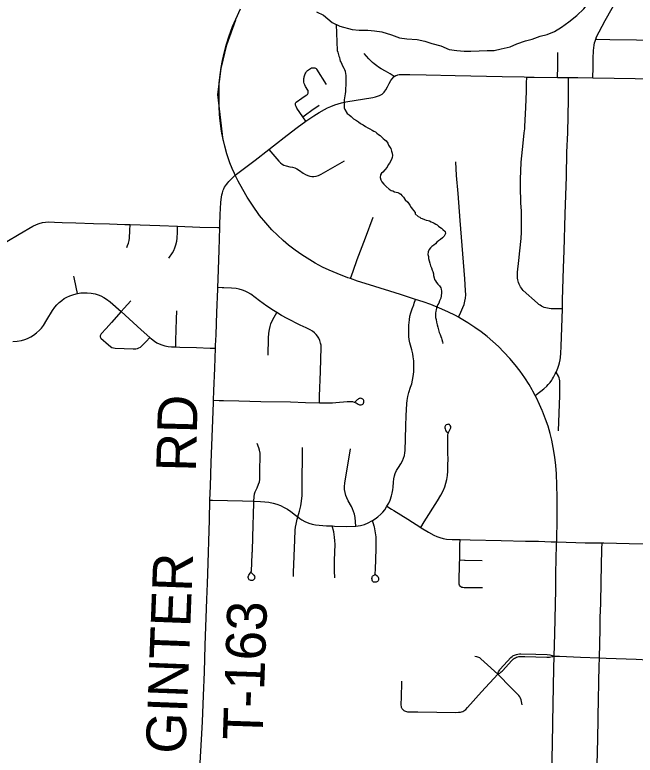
# Model space of a CAD drawing. Extents: x -483 to 680, y 0 to 440.
# Drawn here: x 289.1 to 333.5, y 277.4 to 330.4 of the extents above; entities that cross this region are included whole.
import ezdxf

# ---------------------------------------------------------------- set-up
doc = ezdxf.new("R2010")
doc.units = 0
for name, color, linetype in [('Default', 7, 'Continuous'), ('GM_X_City_Street', 7, 'Continuous'), ('GM_X_County_Road', 7, 'Continuous'), ('GM_X_Major_River', 7, 'Continuous'), ('GM_X_Minor_River', 7, 'Continuous'), ('GM_X_State_Route', 7, 'Continuous'), ('GM_X_Township_Road', 7, 'Continuous'), ('GM_X_Township_Road_Text', 7, 'Continuous')]:
    doc.layers.add(name, color=color, linetype=linetype)

msp = doc.modelspace()

# ---------------------------------------------------------------- linework, layer by layer
at = {"layer": 'Default'}
msp.add_lwpolyline([(304.059, 321.427), (303.678, 324.697), (303.918, 326.545), (304.31, 328.234), (304.975, 330.024)], dxfattribs=at)
at = {"layer": 'GM_X_City_Street'}
for points in [[(330.516, 325.883), (330.519, 326.002), (330.532, 326.498), (330.53, 327.273), (330.558, 327.829), (330.577, 328.017), (330.605, 328.226), (330.636, 328.385), (330.666, 328.504), (330.716, 328.659), (330.778, 328.811), (330.952, 329.171), (331.402, 329.986), (331.883, 330.857), (332.099, 331.245), (332.546, 332.052), (334.247, 335.125), (334.953, 336.404), (335.502, 337.375), (335.718, 337.757), (336.69, 339.528), (337.124, 340.318), (337.77, 341.496), (338.23, 342.335)], [(330.716, 328.659), (330.788, 328.656), (331.719, 328.623), (333.644, 328.598), (335.071, 328.571), (337.473, 328.53), (337.597, 328.527)], [(316.297, 325.978), (316.007, 326.164), (315.668, 326.351), (315.353, 326.526), (315.18, 326.642), (315.049, 326.734), (314.871, 326.876), (314.74, 326.989), (314.577, 327.147), (314.477, 327.249), (314.305, 327.437), (314.149, 327.622)], [(327.982, 325.907), (327.983, 325.985), (327.995, 326.611), (328.007, 327.211), (327.999, 327.702)], [(309.759, 323.098), (309.341, 323.706), (309.271, 323.832), (309.247, 323.881), (309.233, 323.929), (309.227, 323.991), (309.231, 324.031), (309.239, 324.071), (309.255, 324.109), (309.287, 324.149), (309.684, 324.423), (309.995, 324.632), (310.087, 324.701), (310.117, 324.738), (310.136, 324.778), (310.149, 324.827), (310.152, 324.878), (310.146, 324.923), (310.138, 324.969), (310.125, 325.01), (309.957, 325.256), (309.891, 325.377), (309.871, 325.431), (309.855, 325.485), (309.841, 325.562), (309.834, 325.638), (309.831, 325.716), (309.836, 325.793), (309.839, 325.842), (309.847, 325.898), (309.859, 325.957), (309.877, 326.023), (309.903, 326.106), (309.931, 326.175), (309.963, 326.239), (309.993, 326.29), (310.022, 326.328), (310.06, 326.374), (310.1, 326.411), (310.162, 326.459), (310.388, 326.588), (310.443, 326.604), (310.493, 326.61), (310.533, 326.61), (310.583, 326.604), (310.626, 326.592), (310.672, 326.574), (310.702, 326.55), (310.745, 326.504), (311.431, 325.403)], [(328.33, 309.367), (327.997, 309.37), (327.533, 309.374), (327.395, 309.387), (327.27, 309.405), (327.15, 309.433), (327.033, 309.472), (326.926, 309.517), (326.835, 309.567), (326.739, 309.626), (326.643, 309.685), (326.544, 309.763), (325.531, 310.681), (325.456, 310.772), (325.398, 310.853), (325.343, 310.936), (325.278, 311.04), (325.239, 311.128), (325.195, 311.238), (325.158, 311.339), (325.135, 311.448), (325.121, 311.553), (325.111, 311.657), (325.11, 311.734), (325.123, 311.978), (325.217, 312.81), (325.289, 313.523), (325.37, 314.391), (325.399, 314.858), (325.409, 315.42), (325.398, 316.354), (325.368, 316.945), (325.328, 318.124), (325.332, 318.651), (325.347, 319.209), (325.391, 319.859), (325.533, 321.219), (325.606, 321.962), (325.639, 322.239), (325.653, 322.393), (325.723, 323.759), (325.756, 324.94), (325.771, 325.499), (325.79, 325.942)], [(326.389, 303.168), (326.792, 303.48), (327.011, 303.65), (327.213, 303.837), (327.324, 303.951), (327.446, 304.089), (327.569, 304.253), (327.632, 304.353), (327.696, 304.468), (327.826, 304.712), (327.878, 304.83), (327.95, 304.993), (328.005, 305.129), (328.077, 305.327), (328.127, 305.512), (328.174, 305.713), (328.202, 305.889), (328.226, 306.186), (328.255, 306.681), (328.33, 309.367), (328.348, 309.976), (328.417, 312.308), (328.454, 313.52), (328.539, 316.131), (328.617, 318.836), (328.661, 320.577), (328.71, 321.945), (328.772, 324.369), (328.775, 325.396), (328.777, 325.904)], [(309.759, 323.098), (309.947, 323.236), (310.402, 323.573), (310.924, 323.936)], [(309.976, 322.783), (309.818, 323.012), (309.759, 323.098)], [(307.327, 320.762), (307.624, 320.413), (308.048, 319.915), (308.156, 319.809), (308.273, 319.718), (308.401, 319.644), (308.57, 319.579), (308.838, 319.522), (309.023, 319.485), (309.178, 319.442), (309.327, 319.381), (309.517, 319.263), (309.793, 319.061), (309.95, 318.969), (310.115, 318.898), (310.259, 318.858), (310.407, 318.836), (310.556, 318.834), (310.703, 318.853), (310.875, 318.904), (311.067, 318.992), (312.067, 319.561), (312.738, 319.955)], [(320.889, 308.769), (321.053, 309.119), (321.212, 309.455), (321.297, 309.684), (321.361, 309.919), (321.396, 310.129), (321.412, 310.372), (321.402, 310.679), (321.345, 311.516), (321.022, 315.671), (320.866, 317.624), (320.762, 318.895), (320.697, 319.888)], [(288.574, 314.18), (289.452, 314.711), (290.449, 315.278), (290.696, 315.399), (290.896, 315.473), (291.132, 315.534), (291.342, 315.564), (291.586, 315.575), (291.987, 315.563), (292.546, 315.544), (293.509, 315.505), (294.782, 315.469), (295.931, 315.433), (297.017, 315.398), (297.393, 315.386), (299.534, 315.315), (300.801, 315.271), (302.391, 315.215), (303.669, 315.179), (303.818, 315.175)], [(313.164, 311.525), (313.361, 312.066), (313.658, 312.882), (314.242, 314.451), (314.803, 315.929)], [(297.16, 313.749), (297.222, 313.89), (297.289, 314.062), (297.335, 314.241), (297.358, 314.424), (297.378, 314.977), (297.393, 315.386)], [(300.181, 312.979), (300.436, 313.368), (300.526, 313.53), (300.611, 313.729), (300.678, 313.935), (300.741, 314.207), (300.769, 314.422), (300.786, 314.855), (300.801, 315.271)], [(293.642, 310.457), (293.549, 310.903), (293.405, 311.603), (293.384, 311.694)], [(310.945, 302.654), (310.96, 303.117), (311.015, 304.888), (311.047, 305.756), (311.073, 306.593), (311.061, 306.773), (311.033, 306.92), (310.977, 307.092), (310.903, 307.257), (310.81, 307.412), (310.718, 307.529), (310.59, 307.657), (310.448, 307.768), (310.294, 307.862), (309.987, 308.005), (309.561, 308.196), (308.646, 308.664), (308.237, 308.89), (307.89, 309.104), (307.653, 309.249), (307.185, 309.559), (306.651, 309.938), (306.034, 310.405), (305.829, 310.538), (305.639, 310.634), (305.441, 310.71), (305.206, 310.775), (304.996, 310.814), (304.66, 310.842), (304.103, 310.868), (303.979, 310.871), (303.683, 310.879)], [(289.019, 307.027), (289.325, 307.053), (289.628, 307.103), (289.863, 307.167), (290.062, 307.244), (290.308, 307.368), (290.49, 307.478), (290.709, 307.646), (290.914, 307.83), (291.058, 307.987), (291.203, 308.183), (291.452, 308.574), (291.853, 309.243), (292.013, 309.476), (292.154, 309.647), (292.333, 309.827), (292.504, 309.969), (292.689, 310.096), (292.884, 310.207), (293.088, 310.3), (293.299, 310.373), (293.545, 310.439), (293.642, 310.457), (293.886, 310.5), (294.107, 310.518), (294.33, 310.514), (294.612, 310.482), (294.89, 310.428), (295.104, 310.369), (295.312, 310.289), (295.509, 310.186), (295.721, 310.049), (295.971, 309.857), (296.754, 309.166), (298.196, 307.864), (298.822, 307.316), (298.92, 307.23), (299.138, 307.06), (299.317, 306.944), (299.478, 306.861), (299.676, 306.784), (299.883, 306.727), (300.125, 306.683), (300.37, 306.657), (300.665, 306.647), (300.958, 306.636), (302.14, 306.599), (303.134, 306.561), (303.508, 306.546)], [(296.754, 309.166), (296.983, 309.42), (297.208, 309.67), (297.449, 309.948)], [(313.541, 293.821), (313.886, 293.879), (314.18, 293.954), (314.433, 294.063), (314.704, 294.207), (314.754, 294.237), (314.939, 294.352), (315.133, 294.498), (315.339, 294.682), (315.486, 294.836), (315.618, 295.003), (315.78, 295.247), (315.905, 295.471), (316.004, 295.694), (316.107, 295.983), (316.16, 296.189), (316.201, 296.427), (316.218, 296.607), (316.243, 296.979), (316.271, 297.198), (316.318, 297.414), (316.378, 297.595), (316.473, 297.797), (316.605, 298.011), (316.769, 298.27), (316.88, 298.485), (316.961, 298.68), (317.023, 298.882), (317.057, 299.059), (317.075, 299.24), (317.108, 300.073), (317.137, 300.994), (317.158, 301.706), (317.197, 302.604), (317.221, 302.822), (317.273, 303.099), (317.347, 303.372), (317.475, 303.756), (317.549, 303.991), (317.615, 304.258), (317.66, 304.53), (317.69, 304.868), (317.701, 305.3), (317.693, 305.638), (317.663, 305.943), (317.628, 306.154), (317.563, 306.422), (317.417, 306.929), (317.37, 307.176), (317.344, 307.396), (317.336, 307.678), (317.349, 308.209), (317.38, 308.583), (317.42, 308.832), (317.483, 309.077), (317.584, 309.373), (317.696, 309.662), (317.737, 309.777), (317.832, 310.04)], [(300.665, 306.647), (300.68, 307.101), (300.73, 308.624), (300.733, 309.216)], [(296.754, 309.166), (296.061, 308.383), (295.687, 307.967), (295.337, 307.57), (295.288, 307.491), (295.268, 307.433), (295.263, 307.371), (295.278, 307.311), (295.311, 307.259), (295.846, 306.786), (295.991, 306.668), (296.098, 306.606), (296.215, 306.565), (296.338, 306.545), (297.612, 306.509), (297.798, 306.51), (297.92, 306.532), (298.036, 306.575), (298.144, 306.636), (298.266, 306.733), (298.544, 307.025), (298.822, 307.316)], [(307.267, 306.046), (307.31, 307.259), (307.332, 307.632), (307.365, 307.879), (307.413, 308.091), (307.48, 308.298), (307.614, 308.613), (307.792, 308.929), (307.89, 309.104)], [(328.064, 300.638), (328.139, 303.163), (328.159, 304.033), (328.152, 304.222), (328.134, 304.339), (328.101, 304.439), (328.045, 304.553), (327.878, 304.83)], [(303.366, 302.834), (303.773, 302.82), (304.083, 302.809), (305.17, 302.781), (306.754, 302.741), (308.867, 302.704), (309.954, 302.672), (310.945, 302.654), (311.01, 302.653), (311.88, 302.653), (312.128, 302.661), (312.933, 302.734), (313.15, 302.745), (313.304, 302.732), (313.424, 302.701), (313.567, 302.64), (313.727, 302.545), (313.811, 302.506), (313.872, 302.494), (313.934, 302.498), (313.994, 302.513), (314.049, 302.542), (314.094, 302.585), (314.111, 302.612), (314.132, 302.7), (314.126, 302.762), (314.113, 302.81), (314.094, 302.849), (314.057, 302.9), (314.01, 302.939), (313.953, 302.964), (313.892, 302.973), (313.83, 302.965), (313.784, 302.955), (313.744, 302.93), (313.691, 302.889), (313.646, 302.851), (313.49, 302.698)], [(318.201, 293.736), (318.447, 294.13), (319.386, 295.631), (319.642, 296.053), (319.794, 296.355), (319.913, 296.638), (320, 296.9), (320.062, 297.168), (320.103, 297.44), (320.126, 297.747), (320.141, 298.273), (320.148, 298.551), (320.134, 299.112), (320.132, 299.73), (320.126, 300.293), (320.129, 300.357), (320.148, 300.455), (320.172, 300.514), (320.225, 300.622), (320.336, 300.798), (320.354, 300.845), (320.358, 300.892), (320.342, 300.96), (320.309, 301.026), (320.28, 301.056), (320.243, 301.084), (320.197, 301.103), (320.149, 301.109), (320.099, 301.102), (320.027, 301.07), (319.967, 301.019), (319.94, 300.979), (319.924, 300.933), (319.92, 300.857), (319.936, 300.775), (319.968, 300.697), (320, 300.64), (320.05, 300.571), (320.085, 300.535), (320.145, 300.497)], [(306.059, 290.507), (306.156, 290.427), (306.259, 290.33), (306.3, 290.246), (306.313, 290.185), (306.311, 290.124), (306.293, 290.065), (306.26, 290.012), (306.214, 289.97), (306.159, 289.941), (306.099, 289.928), (306.037, 289.931), (305.979, 289.952), (305.928, 289.987), (305.888, 290.035), (305.862, 290.091), (305.851, 290.152), (305.855, 290.213), (305.872, 290.273), (305.901, 290.328), (305.995, 290.452), (306.062, 290.556), (306.082, 290.614), (306.098, 290.705), (306.119, 291.109), (306.145, 291.948), (306.152, 292.009), (306.148, 292.041), (306.155, 292.102), (306.202, 293.906), (306.226, 294.651), (306.251, 295.491), (306.258, 295.608), (306.28, 295.924), (306.308, 296.139), (306.354, 296.287), (306.482, 296.571), (306.597, 296.826), (306.651, 297.004), (306.672, 297.157), (306.69, 297.529), (306.694, 297.934), (306.713, 298.726), (306.696, 299.047), (306.663, 299.252), (306.622, 299.433), (306.482, 299.738)], [(309.401, 294.482), (309.526, 294.887), (309.622, 295.278), (309.672, 295.617), (309.705, 296.019), (309.719, 296.516), (309.736, 299.439)], [(313.541, 293.821), (313.493, 294.433), (313.45, 294.673), (313.393, 294.876), (313.315, 295.075), (313.232, 295.237), (312.992, 295.639), (312.896, 295.839), (312.831, 296.019), (312.778, 296.235), (312.748, 296.456), (312.744, 296.647), (312.769, 296.93), (313.023, 298.466), (313.179, 299.354)], [(303.116, 295.694), (303.284, 295.689), (305.452, 295.628), (306.258, 295.608), (306.728, 295.596), (307.041, 295.574), (307.321, 295.534), (307.628, 295.47), (307.901, 295.392), (308.166, 295.292), (308.423, 295.17), (308.669, 295.03), (308.904, 294.872), (309.224, 294.62), (309.401, 294.482), (309.54, 294.374), (309.692, 294.273), (309.908, 294.163), (310.193, 294.047), (310.426, 293.973), (310.665, 293.924), (310.939, 293.889), (311.463, 293.853), (311.87, 293.839), (312.023, 293.834), (312.862, 293.799), (313.541, 293.821)], [(315.78, 295.247), (316.101, 295.05), (316.26, 294.953), (317.262, 294.33), (318.201, 293.736), (318.232, 293.717), (318.761, 293.388), (319.141, 293.171), (319.342, 293.079), (319.551, 293.005), (319.796, 292.943), (320.046, 292.904), (320.452, 292.877), (321.013, 292.864), (321.726, 292.848), (323.962, 292.796), (325.701, 292.76), (326.632, 292.742), (327.519, 292.715), (327.923, 292.704)], [(309.089, 290.234), (309.095, 290.515), (309.176, 292.85), (309.214, 293.534), (309.238, 293.745), (309.281, 293.974), (309.362, 294.32), (309.401, 294.482)], [(312.048, 290.127), (312.045, 290.22), (312.037, 290.528), (312.031, 290.773), (312.029, 291.05), (312.031, 291.39), (312.044, 291.947), (312.062, 292.535), (312.054, 292.782), (312.026, 293.027), (311.97, 293.409), (311.87, 293.839)], [(314.964, 290.37), (315.086, 290.262), (315.125, 290.218), (315.158, 290.168), (315.18, 290.111), (315.184, 290.049), (315.166, 289.96), (315.149, 289.924), (315.126, 289.895), (315.099, 289.869), (315.045, 289.838), (315.009, 289.825), (314.963, 289.813), (314.914, 289.81), (314.869, 289.817), (314.824, 289.831), (314.786, 289.853), (314.748, 289.902), (314.722, 289.959), (314.709, 290.019), (314.702, 290.075), (314.709, 290.156), (314.719, 290.198), (314.746, 290.249), (314.77, 290.274), (314.853, 290.328), (314.899, 290.356), (314.925, 290.379), (314.944, 290.437), (314.949, 290.733), (315, 292.208), (315.009, 292.552), (315.008, 292.649), (315.008, 292.834), (314.996, 293.059), (314.965, 293.354), (314.892, 293.765), (314.873, 293.828), (314.754, 294.237)], [(320.982, 291.415), (320.993, 292.114), (321.002, 292.457), (321.013, 292.864)], [(327.923, 292.704), (329.958, 292.639), (331.166, 292.627), (331.296, 292.626), (333.099, 292.588), (334.218, 292.573), (334.436, 292.57), (336.549, 292.536)], [(330.796, 275.52), (330.806, 276.016), (330.82, 276.762), (330.858, 278.625), (330.866, 279.092), (330.88, 279.557), (330.893, 280.303), (330.913, 281.328), (330.946, 282.726), (330.972, 283.783), (330.986, 284.406), (331.031, 286.454), (331.045, 287.293), (331.074, 288.287), (331.102, 289.84), (331.156, 292.171), (331.166, 292.627)], [(322.606, 289.407), (321.825, 289.422), (321.298, 289.426), (321.197, 289.43), (321.126, 289.449), (321.061, 289.49), (321.011, 289.54), (320.971, 289.604), (320.95, 289.674), (320.943, 289.807), (320.979, 291.209), (320.982, 291.415)], [(320.982, 291.415), (321.338, 291.399), (321.369, 291.397), (322.58, 291.375)], [(322.064, 284.535), (322.187, 284.513), (322.261, 284.49), (322.323, 284.462), (322.396, 284.422), (322.507, 284.343), (322.742, 284.124), (323.706, 283.242)], [(323.706, 283.242), (323.771, 283.408), (323.812, 283.491), (323.846, 283.545), (323.882, 283.588), (324.634, 284.428), (324.73, 284.511), (324.782, 284.547), (324.837, 284.58), (324.901, 284.611), (324.97, 284.635), (325.051, 284.659), (325.146, 284.68), (325.251, 284.695), (325.354, 284.699), (326.44, 284.674), (327.233, 284.651), (327.429, 284.633), (327.6, 284.587), (327.748, 284.539)], [(323.706, 283.242), (323.864, 283.325), (323.962, 283.398), (324.019, 283.45), (324.044, 283.478), (324.716, 284.218), (324.779, 284.282), (324.829, 284.327), (324.9, 284.375), (324.976, 284.416), (325.049, 284.449), (325.135, 284.477), (325.225, 284.494), (325.316, 284.5), (325.645, 284.495), (327.229, 284.455), (327.417, 284.466), (327.512, 284.477), (327.649, 284.505), (327.748, 284.539)], [(327.748, 284.539), (328.132, 284.524), (329.623, 284.465), (330.986, 284.406), (331.457, 284.385), (333.601, 284.305), (334.046, 284.288), (336.954, 284.211)], [(316.876, 280.761), (316.935, 280.692), (316.993, 280.646), (317.039, 280.614), (317.108, 280.584), (317.17, 280.568), (317.255, 280.555), (317.354, 280.546), (317.98, 280.545), (319.348, 280.531), (320.653, 280.511), (320.906, 280.513), (321.036, 280.528), (321.124, 280.548), (321.199, 280.578), (321.284, 280.627), (321.343, 280.666), (321.412, 280.722), (321.55, 280.855), (322.545, 281.969), (323.706, 283.242)], [(325.465, 281.055), (325.413, 281.288), (325.376, 281.417), (325.333, 281.521), (325.284, 281.61), (325.207, 281.706), (325.084, 281.845), (324.658, 282.259), (323.706, 283.242)], [(316.876, 280.761), (316.846, 280.81), (316.827, 280.859), (316.814, 280.924), (316.804, 281.016), (316.813, 281.634), (316.84, 282.589), (316.838, 282.741)]]:
    msp.add_lwpolyline(points, dxfattribs=at)
at = {"layer": 'GM_X_County_Road'}
for points in [[(316.297, 325.978), (316.423, 326.044), (316.514, 326.08), (316.568, 326.094), (316.649, 326.11), (316.788, 326.124), (317.422, 326.112), (318.585, 326.09), (320.667, 326.043), (322.904, 325.995), (324.026, 325.975), (325.608, 325.947), (325.79, 325.942)], [(309.976, 322.783), (310.553, 323.174), (310.919, 323.406), (311.299, 323.621), (311.522, 323.735), (311.751, 323.839), (312.044, 323.95), (312.283, 324.025), (312.525, 324.09), (312.83, 324.158), (314.777, 324.477), (314.956, 324.516), (315.101, 324.561), (315.24, 324.617), (315.352, 324.671), (315.429, 324.724), (315.509, 324.786), (315.571, 324.849), (315.627, 324.922), (315.7, 325.027), (315.811, 325.234), (315.87, 325.336), (315.944, 325.472), (316.064, 325.691), (316.13, 325.798), (316.297, 325.978)], [(325.79, 325.942), (326.322, 325.928), (327.982, 325.907)], [(327.982, 325.907), (328.188, 325.905), (328.777, 325.904)], [(328.777, 325.904), (329.431, 325.902), (330.516, 325.883)], [(330.516, 325.883), (335.055, 325.806), (336.796, 325.769), (338.18, 325.748)], [(307.327, 320.762), (307.651, 321.014), (308.637, 321.774), (309.351, 322.325), (309.976, 322.783)], [(304.924, 318.92), (305.784, 319.564), (306.351, 320), (307.327, 320.762)]]:
    msp.add_lwpolyline(points, dxfattribs=at)
at = {"layer": 'GM_X_Major_River'}
for points in [[(328.787, 329.882), (329.368, 330.341), (329.873, 330.822), (330.364, 331.436), (330.983, 332.597), (331.303, 333.254), (331.582, 333.759), (331.823, 334.266), (332.087, 334.905), (332.31, 335.449), (332.556, 336.127), (332.838, 336.746), (333.1, 337.328), (333.265, 337.836), (333.488, 338.362), (333.672, 338.87)], [(310.741, 330.613), (311.247, 330.372), (311.858, 329.844), (312.401, 329.583), (313.285, 329.351), (313.796, 329.3), (314.402, 329.303), (314.893, 329.234), (315.403, 329.163), (316.099, 328.956), (316.681, 328.751), (317.21, 328.68), (317.929, 328.624), (318.495, 328.514), (318.983, 328.349), (319.623, 328.162), (320.241, 327.899), (320.789, 327.828), (321.3, 327.796), (321.792, 327.783), (322.381, 327.825), (322.95, 327.829), (323.443, 327.836), (323.939, 327.956), (324.588, 328.11), (325.067, 328.307), (325.699, 328.537), (326.175, 328.639), (326.75, 328.852), (327.246, 328.972), (327.764, 329.206), (328.265, 329.515), (328.787, 329.882)]]:
    msp.add_lwpolyline(points, dxfattribs=at)
at = {"layer": 'GM_X_Minor_River'}
for points in [[(312.15, 329.703), (312.217, 327.832), (312.271, 327.717), (312.303, 327.526), (312.338, 327.429), (312.373, 327.333), (312.408, 327.199), (312.442, 327.084), (312.496, 326.969), (312.549, 326.853), (312.603, 326.737), (312.693, 326.583), (312.729, 326.487), (312.782, 326.352), (312.815, 326.18), (312.83, 326.065), (312.843, 325.856), (312.835, 325.571), (312.829, 325.343), (312.823, 325.153), (312.816, 324.906), (312.792, 324.736), (312.769, 324.603), (312.746, 324.452), (312.722, 324.301), (312.718, 324.168), (312.714, 324.016), (312.71, 323.883), (312.725, 323.73), (312.759, 323.615), (312.942, 323.344), (313.072, 323.245), (313.22, 323.108), (313.386, 322.951), (313.591, 322.831), (313.74, 322.731), (313.889, 322.613), (314.076, 322.513), (314.244, 322.413), (314.412, 322.313), (314.562, 322.232), (314.711, 322.152), (314.842, 322.072), (314.954, 322.012), (315.047, 321.933), (315.177, 321.835), (315.288, 321.755), (315.399, 321.657), (315.51, 321.54), (315.622, 321.461), (315.714, 321.382), (315.842, 321.207), (315.895, 321.072), (315.986, 320.937), (316.059, 320.82), (316.111, 320.648), (316.163, 320.494), (316.177, 320.323), (316.155, 320.19), (316.112, 320.04), (315.953, 319.778), (315.874, 319.666), (315.793, 319.497), (315.635, 319.293), (315.478, 319.126), (315.382, 319.072), (315.321, 318.941), (315.296, 318.751), (315.33, 318.598), (315.42, 318.443), (315.567, 318.268), (315.734, 318.111), (315.937, 317.934), (316.086, 317.835), (316.199, 317.794), (316.311, 317.733), (316.444, 317.711), (316.557, 317.688), (316.651, 317.648), (316.762, 317.568), (316.835, 317.471), (316.965, 317.353), (317.092, 317.16), (317.277, 316.983), (317.404, 316.77), (317.513, 316.615), (317.605, 316.499), (317.678, 316.401), (317.788, 316.265), (317.804, 316.17), (318.007, 315.974), (318.12, 315.913), (318.213, 315.854), (318.307, 315.813), (318.476, 315.751), (318.589, 315.71)], [(318.589, 315.71), (318.721, 315.687), (318.834, 315.646), (318.946, 315.585), (319.059, 315.544), (319.152, 315.484), (319.283, 315.424), (319.376, 315.364), (319.469, 315.285), (319.561, 315.206), (319.673, 315.127), (319.785, 315.048), (319.951, 314.891), (319.966, 314.758), (319.866, 314.57), (319.748, 314.441), (319.612, 314.33), (319.476, 314.22), (319.359, 314.129), (319.261, 314.017), (319.144, 313.907), (318.989, 313.816), (318.892, 313.724), (318.794, 313.613), (318.732, 313.443), (318.707, 313.254), (318.741, 313.101), (318.756, 312.967), (318.789, 312.795), (318.841, 312.623), (318.893, 312.45), (318.964, 312.296), (319.017, 312.142), (319.052, 312.027), (319.104, 311.874), (319.12, 311.759), (319.153, 311.587), (319.187, 311.472), (319.242, 311.375), (319.314, 311.259), (319.424, 311.123), (319.535, 311.006), (319.626, 310.87), (319.661, 310.774), (319.676, 310.64), (319.691, 310.488), (319.623, 310.129), (319.542, 309.941), (319.48, 309.772), (319.42, 309.678), (319.36, 309.566), (319.318, 309.415), (319.295, 309.302), (319.274, 309.207), (319.25, 309.056), (319.246, 308.904), (319.261, 308.751), (319.294, 308.598), (319.326, 308.407), (319.378, 308.215), (319.411, 308.043), (319.463, 307.871), (319.514, 307.679), (319.586, 307.525), (319.639, 307.39), (319.673, 307.275), (319.709, 307.179), (319.761, 307.007), (319.777, 306.911), (319.795, 306.892)]]:
    msp.add_lwpolyline(points, dxfattribs=at)
at = {"layer": 'GM_X_State_Route'}
for points in [[(326.172, 303.568), (325.95, 303.945), (325.643, 304.42), (325.3, 304.907), (324.955, 305.355), (324.572, 305.812), (324.15, 306.277), (323.751, 306.678), (323.359, 307.041), (322.951, 307.386), (322.529, 307.713), (322.069, 308.042), (321.571, 308.369), (321.087, 308.662), (320.889, 308.769), (320.672, 308.886), (320.138, 309.149), (319.537, 309.418), (318.927, 309.666), (318.367, 309.867), (317.832, 310.04), (316.738, 310.395), (314.521, 311.077), (313.68, 311.348), (313.164, 311.525), (312.983, 311.587), (312.205, 311.889), (311.638, 312.129), (311.166, 312.354), (310.65, 312.627), (310.253, 312.86), (309.685, 313.23), (309.207, 313.566), (308.744, 313.923), (308.343, 314.258), (307.936, 314.631), (307.549, 315.026), (307.112, 315.504), (306.666, 316.043), (306.151, 316.783), (305.786, 317.359), (305.472, 317.893), (305.143, 318.491), (304.924, 318.92), (304.862, 319.042), (304.698, 319.406), (304.546, 319.81), (304.329, 320.455), (304.172, 320.99), (304.049, 321.493), (303.961, 321.928), (303.917, 322.24), (303.842, 322.815), (303.804, 323.254), (303.775, 323.822), (303.763, 324.367), (303.762, 325.033), (303.78, 325.535), (303.834, 326.089), (303.907, 326.611), (304.005, 327.128), (304.145, 327.732), (304.3, 328.3), (304.488, 328.89), (304.734, 329.543), (304.965, 330.09), (305.293, 330.817)], [(327.924, 292.754), (327.946, 294.376), (327.951, 295.9), (327.945, 296.757), (327.909, 297.569), (327.868, 298.154), (327.787, 298.762), (327.682, 299.44), (327.577, 299.967), (327.455, 300.454), (327.31, 300.969), (327.123, 301.482), (326.91, 302.039), (326.886, 302.097), (326.702, 302.53), (326.472, 303.013), (326.389, 303.168), (326.221, 303.485), (326.172, 303.568)], [(327.548, 275.621), (327.616, 278.175), (327.644, 279.815), (327.728, 283.645), (327.748, 284.539), (327.784, 286.125), (327.852, 289.3), (327.874, 290.505), (327.896, 291.415), (327.919, 292.551), (327.923, 292.704), (327.924, 292.754)]]:
    msp.add_lwpolyline(points, dxfattribs=at)
at = {"layer": 'GM_X_Township_Road'}
msp.add_line((303.452, 305.115), (303.508, 306.546), dxfattribs=at)
for points in [[(304.065, 317.843), (304.113, 317.949), (304.163, 318.06), (304.223, 318.155), (304.293, 318.26), (304.385, 318.38), (304.464, 318.459), (304.924, 318.92)], [(303.818, 315.175), (303.824, 315.365), (303.849, 316.11), (303.895, 316.968), (303.916, 317.175), (303.938, 317.357), (303.969, 317.517), (304.009, 317.671), (304.065, 317.843)], [(303.683, 310.879), (303.706, 311.485), (303.768, 313.564), (303.818, 315.175)], [(303.508, 306.546), (303.516, 306.738), (303.558, 307.513), (303.614, 309.096), (303.679, 310.771), (303.683, 310.879)], [(303.366, 302.834), (303.394, 303.512), (303.452, 305.115)], [(303.116, 295.694), (303.147, 296.695), (303.203, 298.387), (303.29, 300.799), (303.359, 302.644), (303.366, 302.834)], [(302.888, 288.584), (302.932, 289.727), (302.953, 290.411), (303.072, 294.268), (303.116, 295.694)], [(302.471, 276.182), (302.432, 276.242), (302.414, 276.293), (302.396, 276.337), (302.384, 276.394), (302.378, 276.462), (302.582, 279.828), (302.659, 281.713), (302.713, 283.389), (302.776, 285.312), (302.888, 288.584)]]:
    msp.add_lwpolyline(points, dxfattribs=at)

# ---------------------------------------------------------------- texts
at = {"layer": 'GM_X_Township_Road_Text'}
for s, rotation, p in [('RD', 88.5374, (302.106, 297.694)), ('GINTER', 87.79, (301.356, 277.507)), ('T-163', 88.0478, (306.869, 278.491))]:
    msp.add_text(s, height=2.8409, rotation=rotation, dxfattribs=at).set_placement(p)

doc.saveas('drawing.dxf')
